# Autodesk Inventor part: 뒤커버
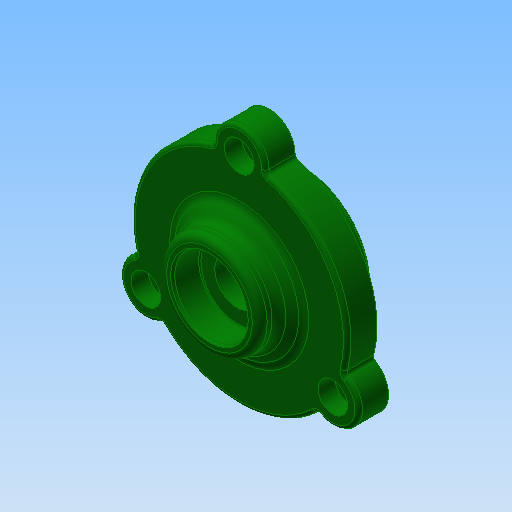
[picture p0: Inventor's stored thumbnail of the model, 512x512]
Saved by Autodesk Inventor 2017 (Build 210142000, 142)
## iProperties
Created: 2016-05
Part Number: 뒤커버
Document SubType Name: Modeling
Designer: mduedu
Density: 2.71 g/cm^3
Material: 알루미늄 6061
Appearance: 진녹색
Author: mduedu
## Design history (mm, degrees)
sketch "스케치1"
  geometry: C1 r 19 at (0, 0); C2 r 29 at (0, 0); 1 further point
  constraints: 2 centre point, 2 coincident
  dimensions: "d33" = 58 diameter of C2; "d34" = 38 diameter of C1
extrude "돌출1" new body sketch "스케치1" distance "d0" = 8; taper "d1" = 0 deg
extrude "돌출2" join sketch "스케치1" distance "d2" = 8; taper "d3" = 0 deg; dims "d35" = 9, "d36" = 0
sketch "스케치5"
  geometry: L1 (-29, 8)-(29, 8) reference; L2 (0, 0)-(0, 15); L3 (-29, 0)-(29, 0) reference; L4 (17.5, 8)-(0, 8); A1 r 25.375 centre (0, -10.375) between (17.5, 8) and (0, 15)
  constraints: 4 end point, 3 point on line, 2 point on circle, 1 centre point, 1 midpoint, 1 perpendicular
  dimensions: "d37" = 17.5 distance from line of L2 L4.start; "d39" = 7 distance from line of L1 L2.end
revolve "회전2" sketch "스케치5" stored, may be unused: angle "d40" = 90 deg
node "작업 평면1"
sketch "스케치6"
  geometry: C1 r 13.5 at (0, 0); 1 further point
  constraints: 1 centre point, 1 coincident
  dimensions: "d42" = 27 diameter of C1
extrude "돌출4" join sketch "스케치6" stored distance "d43" = 10; taper "d44" = 0 deg
sketch "스케치4"
  geometry: L1 (0, -9)-(0, 16); L2 (-15, -9)-(-15, 0); L3 (-15, 0)-(-10, 0); L4 (-10, 0)-(-10, 3); L5 (-10, 3)-(-6, 3); L6 (-6, 3)-(-6, 8.6); L7 (-6, 8.6)-(-10, 8.6); L8 (-10, 8.6)-(-10, 16); L9 (19, -9)-(-19, -9) reference; L10 (-13.5, 16)-(13.5, 16) reference; 1 further point
  constraints: 16 end point, 6 parallel, 3 point on line, 2 midpoint, 1 perpendicular, 1 vertical
  dimensions: "d15" = 30 diameter of L2 L1; "d16" = 20 diameter of L8 L1; "d18" = 9 distance of L2.start L2.end; "d19" = 3 distance of L3.end L4.end; "d20" = 20 diameter of L4 L1; "d21" = 12 diameter of L6 L1; "d45" = 7.4 distance of L7.end L8.end
revolve "회전1" sketch "스케치4" stored, may be unused: angle "d22" = 90 deg
fillet "모깎기2" dims "d23" = 3
fillet "모깎기3" dims "d24" = 0.3
chamfer "모따기2" distance "d46" = 1; stored, may be unused: second distance "d47" = 2, angle "d48" = 45 deg
fillet "모깎기4" dims "d49" = 3
fillet "모깎기5" dims "d50" = 2
sketch "스케치7"
  geometry: C1 r 7 at (0, 29); 2 further points
  constraints: 3 vertical alignment, 1 centre point, 2 other
  dimensions: "d54" = 14 diameter of C1
extrude "돌출5" join sketch "스케치7" stored distance "d55" = 10; taper "d56" = 0 deg
fillet "모깎기6" dims "d57" = 1
fillet "모깎기7" dims "d61" = 1
sketch "스케치8" dims "d62" = 58 (derived)
  geometry: C1 r 18.661 at (0, 0) reference; A1 r 2 centre (-8, 28.914) between (-7.466, 26.986) and (-6, 28.935) reference; A2 r 28 centre (0, 0) between (-7.466, 26.986) and (-27.104, -7.027) reference; A3 r 2 centre (-29.04, -7.529) between (-28.059, -9.272) and (-27.104, -7.027) reference; A4 r 6 centre (-25.115, -14.5) between (-28.059, -9.272) and (-22.059, -19.664) reference; A5 r 2 centre (-21.04, -21.385) between (-19.638, -19.959) and (-22.059, -19.664) reference; A6 r 28 centre (0, 0) between (-19.638, -19.959) and (19.638, -19.959) reference; A7 r 2 centre (21.04, -21.385) between (22.059, -19.664) and (19.638, -19.959) reference; A8 r 6 centre (25.115, -14.5) between (22.059, -19.664) and (28.059, -9.272) reference; A9 r 2 centre (29.04, -7.529) between (27.104, -7.027) and (28.059, -9.272) reference; A10 r 28 centre (0, 0) between (27.104, -7.027) and (7.466, 26.986) reference; A11 r 2 centre (8, 28.914) between (6, 28.935) and (7.466, 26.986) reference; A12 r 6 centre (0, 29) between (6, 28.935) and (-6, 28.935) reference; 4 further points
  constraints: 2 coincident, 1 vertical alignment, 6 other
  dimensions: "d65" = 360 deg dimension on A2.centre point (0, 29) (derived)
sketch "스케치9"
  geometry: A1 r 7 centre (0, 29) between (7, 28.925) and (-7, 28.925) reference; A2 r 7 centre (25.115, -14.5) between (21.55, -20.524) and (28.549, -8.4) reference; A3 r 7 centre (-25.115, -14.5) between (-28.549, -8.4) and (-21.55, -20.524) reference; 3 further points
  constraints: 3 coincident
hole "구멍2" sketch "스케치9" at (-25.115, -14.5), (25.115, -14.5), (0, 29) diameter "d67" = 4.5; stored, may be unused: countersink angle "d71" = 90 deg, drill point angle "d73" = 0 deg; dims "d68" = 6, "d69" = 8, "d70" = 4.6, "d72" = 8
chamfer "모따기3" distance "d76" = 0.7; stored, may be unused: second distance "d77" = 2, angle "d78" = 30 deg
node "솔리드1"
pattern_circular "원형 패턴1" dims angle "d59" = 360 deg
other parameters: "d41" = 8
